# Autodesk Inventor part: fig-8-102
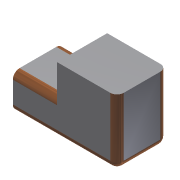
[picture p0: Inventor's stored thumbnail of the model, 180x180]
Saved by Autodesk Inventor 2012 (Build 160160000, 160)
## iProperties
Shininess: 64.0
Length Units: 11269
Angle Units: 11279
Time Units: 11290
Mass Units: 11283
Length Display Precision: 3
Angle Display Precision: 2
Compacted: True
Part Number: fig-8-102
Document SubType Name: Modeling
Created: 2002-12
Designer: deepak
Density: 1 g/cm^3
Material: Default
Density: 0.0
Volumn: 0.0
Area: 0.0
PropertySet Name: Model Information
Control State: 0
Master: False
Checked Out: False
Author: deepak
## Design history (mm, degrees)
sketch "Sketch1"
  geometry: L1 (-26.972, 23.346)-(8.906, 23.346); L2 (8.906, 23.346)-(8.906, 5.025); L3 (8.906, -15.84)-(-26.972, -15.84); L4 (-26.972, -15.84)-(-26.972, 23.346); L5 (8.906, -15.84)-(35.369, -15.84); L6 (35.369, -15.84)-(35.369, 5.025); L7 (35.369, 5.025)-(8.906, 5.025)
  constraints: 14 end point, 3 parallel, 2 horizontal, 2 perpendicular
extrude "Extrusion1" new body sketch "Sketch1" stored distance "d0" = 30; taper "d1" = 0 deg
fillet "Fillet1" dims "d2" = 4, "d3" = 4
delete_face "Delete Face1"
delete_face "Delete Face2"
delete_face "Delete Face3"
body "Solid1"
